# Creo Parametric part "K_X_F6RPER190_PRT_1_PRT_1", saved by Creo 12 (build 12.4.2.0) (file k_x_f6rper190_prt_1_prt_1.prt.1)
Units: Custom; MM, KILOGRAM, SECS

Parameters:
  PTC_WM_ITERATION = "0"
  PTC_WM_VERSION = "-.0"
  PTC_WM_LIFECYCLE_STATE = "In Work"
  PTC_WM_LIFECYCLE = "MO_CADDocument"
  PTC_WM_CREATED_BY = "Maximilian Roepper (Z0017RMS: MO)"
  PTC_WM_CREATED_ON = "18-Sep-26 11:36:42 AM"
  PTC_WM_MODIFIED_BY = "Maximilian Roepper (Z0017RMS: MO)"
  PTC_WM_MODIFIED_ON = "18-Sep-26 11:36:46 AM"
  PDMLINKNUMBER = "PDM000071454766"
  PTC_WM_NAME = "k_x_f6rper190_prt_1_prt_1.prt"
  PTC_WM_NUMBER = "PDM000071454766"

Other parameters: WEIGHT, WEIGHT_FACTOR, WEIGHT_ADD, _MASS_TEMP, _DIFF_TEMP, MC_ERRORS, SUPPLIER

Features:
  1. coordinate system
  2. datum plane "PRT_YZ"
  3. datum plane "PRT_XY"
  4. datum plane "PRT_XZ"
  5. coordinate system
  6. datum axis
  7. datum axis
  8. datum axis
  9. coordinate system
  10. imported feature
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
Other named items: PRT, SIEMENS_MO, DRW_VIEW_ORG, PRT_X, PRT_Y, PRT_Z, CS0, ROUGH_GROB

Layers: 00_STD_CSYS-KSYS, 01_STD_PLANES-EBENEN, 02_STD_AXES-ACHSEN, 03_STD_CSYS-KSYS, 24_IMPORT_FEAT-IMPORT_KE

Surfaces: 20 tabulated cylinder, 4 plane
